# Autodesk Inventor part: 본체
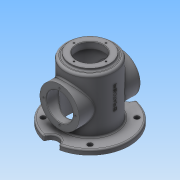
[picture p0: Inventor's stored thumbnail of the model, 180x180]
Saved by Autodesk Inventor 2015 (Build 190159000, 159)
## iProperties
Created: 2018-04
Part Number: 본체
Material: 일반
Document SubType Name: Modeling
Designer: SCD-A04
Density: 1 g/cm^3
Appearance: 기본값
Author: SCD-A04
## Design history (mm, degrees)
sketch "스케치1"
  geometry: C1 r 80 at (0, 0); 1 further point
  constraints: 1 centre point, 1 coincident
  dimensions: "d0" = 160 diameter of C1
extrude "돌출1" new body sketch "스케치1" distance "d1" = 10; taper "d2" = 0 deg
sketch "스케치2"
  geometry: C1 r 80 at (0, 0) reference; C2 r 50 at (0, 0)
  constraints: 1 centre point, 1 coincident
  dimensions: "d3" = 100 diameter of C2
extrude "돌출2" join sketch "스케치2" distance "d4" = 8; taper "d5" = 0 deg
sketch "스케치3"
  geometry: C1 r 80 at (0, 0) reference; C2 r 50 at (0, 0)
  constraints: 1 centre point, 1 coincident
  dimensions: "d6" = 100 diameter of C2
extrude "돌출3" join sketch "스케치3" distance "d7" = 110; taper "d8" = 0 deg
sketch "스케치4"
  geometry: C1 r 50 at (0, 0) reference; C2 r 40 at (0, 0)
  constraints: 1 centre point, 1 coincident
  dimensions: "d9" = 80 diameter of C2
extrude "돌출4" join sketch "스케치4" distance "d10" = 5; taper "d11" = 0 deg
node "작업 평면1"
sketch "스케치5"
  geometry: L1 (-80, 0)-(80, 0) reference; C1 r 40 at (0, 60); 1 further point
  constraints: 1 centre point, 1 vertical alignment
  dimensions: "d13" = 80 diameter of C1; "d14" = 60 distance from line of L1 C1.centre
extrude "돌출5" join sketch "스케치5" distance "d15" = 124; taper "d16" = 0 deg
hole "구멍1" diameter "d19" = 90; stored, may be unused: countersink angle "d23" = 90 deg, drill point angle "d25" = 0 deg; dims "d17" = 10, "d18" = 10, "d20" = 6, "d21" = 4, "d22" = 2, "d24" = 120
hole "구멍2" diameter "d28" = 54; stored, may be unused: countersink angle "d32" = 90 deg, drill point angle "d34" = 0 deg; dims "d26" = 10, "d27" = 10, "d29" = 6, "d30" = 4, "d31" = 2, "d33" = 120
hole "구멍3" diameter "d37" = 54; stored, may be unused: countersink angle "d41" = 90 deg, drill point angle "d43" = 0 deg; dims "d35" = 10, "d36" = 10, "d38" = 6, "d39" = 4, "d40" = 2, "d42" = 120
sketch "스케치6"
  geometry: C1 r 15 at (0, -80); 1 further point
  constraints: 1 centre point, 1 vertical alignment, 1 other
  dimensions: "d44" = 30 diameter of C1
extrude "돌출6" cut sketch "스케치6" stored distance "d45" = 124; taper "d46" = 0 deg
sketch "스케치7"
  geometry: C1 r 27 at (0, 0) reference; 2 further points
  dimensions: "d47" = 32.5 distance of C1.centre point (0, 32.5)
hole "구멍4" sketch "스케치7" at (0, 32.5) diameter "d48" = 3.242; stored, may be unused: countersink angle "d52" = 90 deg, drill point angle "d54" = 118 deg; dims "d49" = 8, "d50" = 4, "d51" = 2, "d53" = 10
sketch "스케치8"
  geometry: C1 r 27 at (0, 0) reference; 1 further point
  dimensions: "d58" = 32.5 distance of C1.centre point (-32.5, 0)
hole "구멍5" sketch "스케치8" at (-32.5, 0) diameter "d59" = 3.242; stored, may be unused: countersink angle "d63" = 90 deg, drill point angle "d65" = 118 deg; dims "d60" = 8, "d61" = 4, "d62" = 2, "d64" = 10
fillet "모깎기1" dims "d69" = 5
fillet "모깎기2" dims "d70" = 3
fillet "모깎기3" dims "d71" = 3
fillet "모깎기4" dims "d72" = 3
fillet "모깎기5" dims "d73" = 3
chamfer "모따기1" distance "d74" = 1; stored, may be unused: second distance "d75" = 2, angle "d76" = 45 deg
fillet "모깎기6" dims "d77" = 3
sketch "스케치9" dims "d80" = 135
  geometry: L1 (0, 0)-(47.73, -47.73); L2 (0, 0)-(39.455, 0); C1 r 5 at (47.73, -47.73); A1 r 77 centre (0, 0) between (17.301, -75.031) and (17.301, 75.031) reference; 1 further point
  constraints: 4 end point, 2 coincident, 1 centre point, 1 horizontal, 3 other
  dimensions: "d78" = 45 deg angle of L2 L1; "d81" = 10 diameter of C1
extrude "돌출7" cut sketch "스케치9" distance "d82" = 124; taper "d83" = 0 deg
node "작업 평면2"
sketch "스케치10"
  geometry: L1 (-77.955, 0)-(77.955, 0) reference; 2 further points
  constraints: 1 other
  dimensions: "d88" = 70 distance from line of point (0.578, 70) L1
feature "엠보싱1" sketch "스케치10" dims "d89" = 0.5, "d90" = 0
fillet "모깎기7" dims "d91" = 3
node "솔리드1"
mirror "대칭1"
pattern_circular "원형 패턴1" dims angle "d56" = 360 deg
mirror "대칭2"
pattern_circular "원형 패턴2" dims angle "d67" = 360 deg
pattern_circular "원형 패턴3" dims angle "d85" = 360 deg
other parameters: "d12" = -62, "d87" = 97.75
